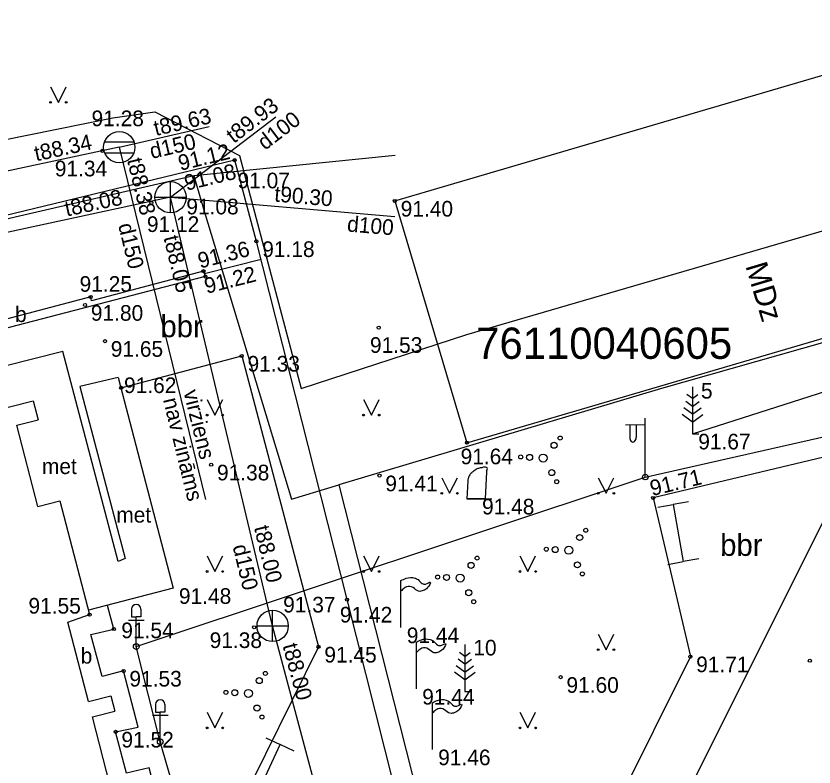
# Model space of a CAD drawing. Extents: x 634272 to 634544, y 247463 to 247653.
# Drawn here: x 634418.64 to 634444.15, y 247588.75 to 247612.76 of the extents above; entities that cross this region are included whole.
import ezdxf

# ---------------------------------------------------------------- set-up
doc = ezdxf.new("R2010")
doc.units = 0
for name, color, linetype in [('APGS_ELEM_####_####_#', 7, 'Continuous'), ('APGS_VADP_ZSPR_####_#', 7, 'Continuous'), ('BUVE_BDET_####_####_#', 7, 'Continuous'), ('BUVE_BDET_####_TKST_#', 7, 'Continuous'), ('BUVE_EKAS_####_####_#', 7, 'Continuous'), ('BUVE_EKAS_RAKS_TKST_#', 7, 'Continuous'), ('BUVE_ELEM_####_####_#', 7, 'Continuous'), ('BUVE_SOLS_####_####_#', 7, 'Continuous'), ('CELI_CAPM_####_####_#', 7, 'Continuous'), ('CELI_CMAL_####_####_#', 7, 'Continuous'), ('CELI_CSEG_####_TKST_#', 7, 'Continuous'), ('LKAN_ELEM_####_####_#', 7, 'Continuous'), ('LKAN_ELEM_PAST_TKST_#', 7, 'Continuous'), ('LKAN_VADP_PAST_####_#', 7, 'Continuous'), ('LKAN_VADP_PAST_TKST_#', 7, 'Continuous'), ('RAMI_UZMR_####_####_#', 7, 'Continuous'), ('RELJ_AATZ_####_TKST_#', 7, 'Continuous'), ('RELJ_ELEM_####_####_#', 7, 'Continuous'), ('ROBZ_KADS_####_TKST_#', 7, 'Continuous'), ('ROBZ_UZMR_####_####_#', 7, 'Continuous'), ('SKAN_ELEM_####_####_#', 7, 'Continuous'), ('SKAN_ELEM_PAST_TKST_#', 7, 'Continuous'), ('SKAN_VADP_PAST_####_#', 7, 'Continuous'), ('SKAN_VADP_PAST_TKST_#', 7, 'Continuous'), ('TERT_DIAM_####_TKST_#', 7, 'Continuous'), ('TERT_ELEM_####_####_#', 7, 'Continuous'), ('TERT_KOKR_####_####_#', 7, 'Continuous')]:
    doc.layers.add(name, color=color, linetype=linetype)

msp = doc.modelspace()

# ---------------------------------------------------------------- linework, layer by layer
at = {"layer": 'APGS_ELEM_####_####_#'}
for p, q in [((634438.755, 247599.687), (634438.12, 247599.682)), ((634438.255, 247599.683), (634438.255, 247599.291)), ((634438.465, 247599.685), (634438.465, 247599.291)), ((634438.755, 247598.02), (634438.755, 247599.903)), ((634422.337, 247593.799), (634422.337, 247593.549)), ((634422.337, 247593.549), (634422.487, 247593.549)), ((634422.487, 247592.599), (634422.487, 247593.549)), ((634422.637, 247593.549), (634422.487, 247593.549)), ((634422.637, 247593.799), (634422.637, 247593.549)), ((634422.237, 247593.449), (634422.737, 247593.449)), ((634423.105, 247590.752), (634423.105, 247590.502)), ((634423.405, 247590.752), (634423.405, 247590.502)), ((634423.105, 247590.502), (634423.255, 247590.502)), ((634423.255, 247589.552), (634423.255, 247590.502)), ((634423.405, 247590.502), (634423.255, 247590.502)), ((634423.005, 247590.402), (634423.505, 247590.402))]:
    msp.add_line(p, q, dxfattribs=at)
for centre, radius in [((634438.755, 247598.02), 0.09), ((634422.487, 247592.599), 0.0907), ((634423.255, 247589.552), 0.0907)]:
    msp.add_circle(centre, radius, dxfattribs=at)
for centre in [(634422.487, 247593.799), (634423.255, 247590.752)]:
    msp.add_arc(centre, 0.15, 0, 180, dxfattribs=at)
msp.add_ellipse((634438.36, 247599.291), major_axis=(0, 0.151), ratio=0.695971, start_param=1.570796, end_param=4.712389, dxfattribs=at)
at = {"layer": 'APGS_VADP_ZSPR_####_#'}
msp.add_lwpolyline([(634424.64, 247564.493), (634427.489, 247567.387), (634428.243, 247568.282), (634428.556, 247569.174), (634428.62, 247569.734), (634428.349, 247570.951), (634427.518, 247573.97), (634425.055, 247583.293), (634424.177, 247586.368), (634423.255, 247589.552), (634422.487, 247592.599), (634438.755, 247598.02), (634453.341, 247601.325), (634455.217, 247592.645), (634458.049, 247580.186), (634460.842, 247567.679), (634446.181, 247564.209)], dxfattribs=at)
at = {"layer": 'BUVE_BDET_####_####_#'}
msp.add_line((634421.062, 247603.658), (634421.031, 247603.777), dxfattribs=at)
for points in [[(634424.638, 247604.603), (634424.692, 247604.432), (634415.797, 247602.116)], [(634424.638, 247604.603), (634421.062, 247603.658)], [(634421.031, 247603.777), (634409.625, 247600.763)], [(634421.911, 247601.206), (634420.687, 247600.92), (634422.13, 247595.421), (634421.912, 247595.323), (634420.138, 247602.03), (634413.732, 247600.418), (634413.69, 247600.52), (634416.369, 247601.213)], [(634421.911, 247601.206), (634423.665, 247594.465), (634420.962, 247593.759)], [(634421.77, 247593.16), (634421.573, 247593.918)], [(634424.519, 247582.466), (634423.79, 247582.308), (634423.459, 247583.653), (634424.19, 247583.849), (634423.711, 247585.639), (634422.99, 247585.469), (634422.619, 247586.777), (634423.356, 247586.952), (634422.897, 247588.72), (634422.18, 247588.555), (634421.828, 247589.872), (634422.546, 247590.02), (634422.083, 247591.821), (634421.394, 247591.641), (634421.036, 247592.981), (634421.77, 247593.16)]]:
    msp.add_lwpolyline(points, dxfattribs=at)
at = {"layer": 'BUVE_EKAS_####_####_#'}
for p, q in [((634418.676, 247599.674), (634419.357, 247599.85)), ((634419.347, 247597.079), (634420.043, 247597.259)), ((634420.958, 247590.842), (634420.303, 247593.378)), ((634420.958, 247590.842), (634421.671, 247591.026)), ((634421.085, 247590.354), (634421.798, 247590.538)), ((634421.763, 247587.727), (634421.085, 247590.354))]:
    msp.add_line(p, q, dxfattribs=at)
for points in [[(634430.752, 247606.848), (634450.886, 247612.763)], [(634430.752, 247606.848), (634433.054, 247599.119)], [(634433.054, 247599.119), (634453.188, 247605.034)], [(634410.243, 247598.168), (634413.566, 247598.866), (634413.511, 247599.021), (634419.188, 247600.462)], [(634419.188, 247600.462), (634419.357, 247599.85)], [(634419.347, 247597.079), (634418.676, 247599.674)], [(634420.043, 247597.259), (634420.998, 247593.62)], [(634420.303, 247593.378), (634420.998, 247593.62)], [(634421.671, 247591.026), (634421.798, 247590.538)]]:
    msp.add_lwpolyline(points, dxfattribs=at)
at = {"layer": 'BUVE_ELEM_####_####_#'}
for p, q in [((634430.947, 247594.372), (634430.947, 247594.709)), ((634430.947, 247593.209), (634430.947, 247594.372)), ((634431.44, 247592.407), (634431.44, 247592.744)), ((634431.44, 247591.244), (634431.44, 247592.407)), ((634431.95, 247590.469), (634431.95, 247590.806)), ((634431.95, 247589.306), (634431.95, 247590.469))]:
    msp.add_line(p, q, dxfattribs=at)
for points in [[(634430.947, 247594.709), (634431.109, 247594.783), (634431.385, 247594.792), (634431.491, 247594.739), (634431.628, 247594.612), (634431.733, 247594.6), (634431.883, 247594.657), (634431.797, 247594.485), (634431.66, 247594.39), (634431.508, 247594.369), (634431.332, 247594.485), (634431.12, 247594.511), (634431.052, 247594.47), (634430.947, 247594.372)], [(634431.44, 247592.744), (634431.602, 247592.818), (634431.878, 247592.827), (634431.984, 247592.774), (634432.121, 247592.647), (634432.226, 247592.635), (634432.376, 247592.692), (634432.29, 247592.52), (634432.153, 247592.425), (634432.001, 247592.404), (634431.825, 247592.52), (634431.613, 247592.546), (634431.545, 247592.505), (634431.44, 247592.407)], [(634431.95, 247590.806), (634432.112, 247590.88), (634432.388, 247590.889), (634432.494, 247590.836), (634432.631, 247590.709), (634432.736, 247590.697), (634432.886, 247590.754), (634432.8, 247590.582), (634432.663, 247590.487), (634432.511, 247590.466), (634432.335, 247590.582), (634432.123, 247590.608), (634432.055, 247590.567), (634431.95, 247590.469)]]:
    msp.add_spline(points, degree=3, dxfattribs=at)
at = {"layer": 'BUVE_SOLS_####_####_#'}
for p, q in [((634439.151, 247597.057), (634439.643, 247597.144)), ((634440.135, 247597.231), (634439.643, 247597.144)), ((634440.46, 247595.402), (634439.968, 247595.315)), ((634439.476, 247595.228), (634439.968, 247595.315)), ((634426.627, 247589.678), (634427.081, 247589.469)), ((634427.535, 247589.26), (634427.081, 247589.469))]:
    msp.add_line(p, q, dxfattribs=at)
for points in [[(634439.643, 247597.144), (634439.968, 247595.315)], [(634426.297, 247587.764), (634427.081, 247589.469)]]:
    msp.add_lwpolyline(points, dxfattribs=at)
at = {"layer": 'CELI_CAPM_####_####_#'}
msp.add_lwpolyline([(634426.327, 247605.556), (634425.634, 247608.152), (634408.658, 247604.045)], dxfattribs=at)
at = {"layer": 'CELI_CMAL_####_####_#'}
msp.add_line((634426.474, 247604.975), (634424.665, 247604.518), dxfattribs=at)
for points in [[(634429.222, 247594.101), (634426.327, 247605.556)], [(634422.006, 247600.872), (634425.858, 247601.892), (634428.312, 247592.59), (634425.762, 247587.434), (634427.131, 247582.006)], [(634454.07, 247600.948), (634439.005, 247597.351), (634440.194, 247592.28), (634435.446, 247582.728), (634431.634, 247584.56), (634429.222, 247594.101)], [(634454.416, 247599.108), (634444.542, 247596.807), (634437.329, 247582.391), (634445.746, 247584.585), (634452.082, 247586.129), (634455.906, 247592.579)]]:
    msp.add_lwpolyline(points, dxfattribs=at)
at = {"layer": 'LKAN_ELEM_####_####_#'}
for p, q in [((634421.478, 247608.741), (634422.414, 247608.741)), ((634421.478, 247608.391), (634422.414, 247608.391))]:
    msp.add_line(p, q, dxfattribs=at)
msp.add_circle((634421.946, 247608.566), 0.5, dxfattribs=at)
at = {"layer": 'LKAN_VADP_PAST_####_#'}
msp.add_line((634421.946, 247608.566), (634424.7, 247597.301), dxfattribs=at)
for points in [[(634421.946, 247608.566), (634424.816, 247609.232)], [(634421.946, 247608.566), (634397.803, 247603.4), (634400.101, 247595.54), (634405.793, 247582.831), (634408.48, 247579.25)]]:
    msp.add_lwpolyline(points, dxfattribs=at)
at = {"layer": 'RAMI_UZMR_####_####_#'}
msp.add_lwpolyline([(634357.63, 247590.775), (634379.264, 247596.642), (634392.424, 247602.216), (634402.994, 247605.715), (634421.735, 247609.504), (634423.082, 247609.702), (634425.783, 247608.304), (634427.755, 247600.855), (634433.048, 247602.581), (634454.806, 247608.92), (634459.819, 247587.798), (634462.766, 247575.147), (634466.614, 247558.36), (634469.076, 247546.545)], dxfattribs=at)
at = {"layer": 'RELJ_ELEM_####_####_#'}
for centre in [(634421.401, 247608.452), (634425.634, 247608.152), (634422.972, 247606.785), (634430.752, 247606.848), (634426.327, 247605.556), (634424.638, 247604.603), (634424.692, 247604.432), (634421.031, 247603.777), (634420.851, 247603.518), (634430.234, 247602.798), (634421.487, 247602.366), (634425.858, 247601.892), (634422.006, 247600.872), (634433.054, 247599.119), (634424.881, 247598.414), (634430.26, 247598.065), (634439.005, 247597.351), (634429.222, 247594.101), (634420.998, 247593.62), (634421.77, 247593.16), (634426.257, 247593.218), (634428.312, 247592.59), (634440.194, 247592.28), (634444.013, 247592.146), (634422.083, 247591.821), (634436.049, 247591.622), (634421.828, 247589.872)]:
    msp.add_circle(centre, 0.05, dxfattribs=at)
at = {"layer": 'ROBZ_UZMR_####_####_#'}
for points in [[(634430.762, 247608.303), (634424.328, 247607.646)], [(634424.328, 247607.646), (634404.114, 247602.967)], [(634424.328, 247607.646), (634424.669, 247606.492)], [(634424.669, 247606.492), (634427.447, 247597.318)], [(634453.433, 247604.869), (634439.274, 247600.849)], [(634439.274, 247600.849), (634428.96, 247597.768)], [(634427.447, 247597.318), (634428.96, 247597.768)], [(634428.96, 247597.768), (634439.705, 247555.341)]]:
    msp.add_lwpolyline(points, dxfattribs=at)
at = {"layer": 'SKAN_ELEM_####_####_#'}
for p, q in [((634423.583, 247606.465), (634423.583, 247607.465)), ((634423.083, 247606.965), (634424.083, 247606.965)), ((634426.846, 247592.759), (634426.846, 247593.759)), ((634426.346, 247593.259), (634427.346, 247593.259))]:
    msp.add_line(p, q, dxfattribs=at)
for centre in [(634423.583, 247606.965), (634426.846, 247593.259)]:
    msp.add_circle(centre, 0.5, dxfattribs=at)
at = {"layer": 'SKAN_VADP_PAST_####_#'}
for q in [(634426.952, 247609.533), (634430.752, 247606.348)]:
    msp.add_line((634423.583, 247606.965), q, dxfattribs=at)
msp.add_lwpolyline([(634467.293, 247556.065), (634460.247, 247556.807), (634435.579, 247559.128), (634432.448, 247572.232), (634426.846, 247593.259), (634423.583, 247606.965), (634413.214, 247604.726), (634403.305, 247602.476), (634405.576, 247593.489), (634409.131, 247581.899)], dxfattribs=at)
at = {"layer": 'TERT_ELEM_####_####_#'}
for p, q in [((634419.75, 247610.5), (634420, 247610)), ((634420, 247610), (634420.25, 247610.5)), ((634440.261, 247600.904), (634440.261, 247599.404)), ((634424.75, 247600.5), (634425, 247600)), ((634425, 247600), (634425.25, 247600.5)), ((634429.75, 247600.5), (634430, 247600)), ((634430, 247600), (634430.25, 247600.5)), ((634440.261, 247600.278), (634440.045, 247600.436)), ((634440.261, 247600.528), (634440.085, 247600.656)), ((634440.261, 247600.528), (634440.435, 247600.656)), ((634440.261, 247600.278), (634440.477, 247600.436)), ((634440.261, 247600.028), (634439.983, 247600.232)), ((634440.261, 247600.028), (634440.539, 247600.232)), ((634440.261, 247599.778), (634439.929, 247600.022)), ((634440.261, 247599.778), (634440.595, 247600.022)), ((634440.261, 247599.404), (634440.461, 247599.404)), ((634433.652, 247597.325), (634433.686, 247598.19)), ((634432.25, 247598), (634432.5, 247597.5)), ((634432.5, 247597.5), (634432.75, 247598)), ((634433.083, 247597.898), (634433.052, 247597.325)), ((634437.25, 247598), (634437.5, 247597.5)), ((634437.5, 247597.5), (634437.75, 247598)), ((634433.652, 247597.325), (634433.052, 247597.325)), ((634433.052, 247597.325), (634433.352, 247597.325)), ((634433.352, 247597.325), (634433.652, 247597.325)), ((634433.652, 247597.325), (634433.852, 247597.325)), ((634424.75, 247595.5), (634425, 247595)), ((634425, 247595), (634425.25, 247595.5)), ((634429.75, 247595.5), (634430, 247595)), ((634430, 247595), (634430.25, 247595.5)), ((634434.75, 247595.5), (634435, 247595)), ((634435, 247595), (634435.25, 247595.5)), ((634437.25, 247593), (634437.5, 247592.5)), ((634437.5, 247592.5), (634437.75, 247593)), ((634432.988, 247592.661), (634432.988, 247591.161)), ((634432.988, 247592.285), (634432.812, 247592.413)), ((634432.988, 247592.285), (634433.162, 247592.413)), ((634432.988, 247592.035), (634432.772, 247592.193)), ((634432.988, 247592.035), (634433.204, 247592.193)), ((634432.988, 247591.535), (634432.656, 247591.779)), ((634432.988, 247591.785), (634432.71, 247591.989)), ((634432.988, 247591.785), (634433.266, 247591.989)), ((634432.988, 247591.535), (634433.322, 247591.779)), ((634432.988, 247591.161), (634433.188, 247591.161)), ((634424.75, 247590.5), (634425, 247590)), ((634425, 247590), (634425.25, 247590.5)), ((634434.75, 247590.5), (634435, 247590)), ((634435, 247590), (634435.25, 247590.5))]:
    msp.add_line(p, q, dxfattribs=at)
for centre, radius in [((634419.75, 247610), 0.028), ((634420.25, 247610), 0.0263), ((634424.75, 247600), 0.028), ((634425.25, 247600), 0.0263), ((634429.75, 247600), 0.028), ((634430.25, 247600), 0.0263), ((634436.034, 247599.267), 0.064), ((634435.838, 247599.036), 0.096), ((634434.772, 247598.662), 0.064), ((634435.056, 247598.649), 0.096), ((634435.49, 247598.628), 0.128), ((634435.766, 247598.161), 0.096), ((634435.924, 247597.872), 0.064), ((634432.25, 247597.5), 0.028), ((634432.75, 247597.5), 0.0263), ((634437.25, 247597.5), 0.028), ((634437.75, 247597.5), 0.0263), ((634436.853, 247596.318), 0.064), ((634436.657, 247596.087), 0.096), ((634435.591, 247595.713), 0.064), ((634435.875, 247595.7), 0.096), ((634436.309, 247595.679), 0.128), ((634433.381, 247595.428), 0.064), ((634433.185, 247595.197), 0.096), ((634436.585, 247595.212), 0.096), ((634424.75, 247595), 0.028), ((634425.25, 247595), 0.0263), ((634429.75, 247595), 0.028), ((634430.25, 247595), 0.0263), ((634432.119, 247594.823), 0.064), ((634432.403, 247594.81), 0.096), ((634432.837, 247594.789), 0.128), ((634434.75, 247595), 0.028), ((634435.25, 247595), 0.0263), ((634436.743, 247594.923), 0.064), ((634433.113, 247594.322), 0.096), ((634433.271, 247594.033), 0.064), ((634437.25, 247592.5), 0.028), ((634437.75, 247592.5), 0.0263), ((634426.614, 247591.741), 0.064), ((634426.418, 247591.51), 0.096), ((634425.352, 247591.136), 0.064), ((634425.636, 247591.123), 0.096), ((634426.07, 247591.102), 0.128), ((634426.346, 247590.635), 0.096), ((634426.504, 247590.346), 0.064), ((634424.75, 247590), 0.028), ((634425.25, 247590), 0.0263), ((634434.75, 247590), 0.028), ((634435.25, 247590), 0.0263)]:
    msp.add_circle(centre, radius, dxfattribs=at)
msp.add_spline([(634433.686, 247598.19), (634433.69, 247598.221), (634433.693, 247598.232), (634433.708, 247598.294), (634433.678, 247598.329), (634433.556, 247598.323), (634433.452, 247598.305), (634433.346, 247598.266), (634433.281, 247598.222), (634433.206, 247598.158), (634433.126, 247598.06), (634433.095, 247597.971), (634433.083, 247597.897)], degree=3, dxfattribs=at)
at = {"layer": 'TERT_KOKR_####_####_#'}
msp.add_lwpolyline([(634440.261, 247599.404), (634452.282, 247603.254)], dxfattribs=at)

# ---------------------------------------------------------------- texts
at = {"layer": 'BUVE_BDET_####_TKST_#'}
for s, p in [('b', (634418.615, 247602.976)), ('met', (634419.473, 247598.116)), ('met', (634421.849, 247596.563)), ('b', (634420.711, 247592.056))]:
    msp.add_text(s, height=0.5, dxfattribs=at).set_placement(p)
at = {"layer": 'BUVE_EKAS_RAKS_TKST_#'}
msp.add_text('MDz', height=0.7, rotation=286.5856, dxfattribs=at).set_placement((634441.949, 247604.775))
at = {"layer": 'CELI_CSEG_####_TKST_#'}
for p in [(634423.261, 247602.491), (634441.148, 247595.499)]:
    msp.add_text('bbr', height=0.7, dxfattribs=at).set_placement(p)
at = {"layer": 'LKAN_ELEM_PAST_TKST_#'}
msp.add_text(' 91.28', height=0.5, dxfattribs=at).set_placement((634420.873, 247609.239))
at = {"layer": 'LKAN_VADP_PAST_TKST_#'}
for s, rotation, p in [('t89.63', 13.0594, (634423.111, 247608.923)), ('t88.34', 12.0777, (634419.288, 247608.113)), ('d150', 13.0594, (634422.981, 247608.19)), ('t88.38', 283.7385, (634422.19, 247608.158)), ('d150', 283.7385, (634421.906, 247606.078)), ('virziens', 283.7385, (634423.992, 247600.749)), ('nav zināms', 283.7385, (634423.34, 247600.496))]:
    msp.add_text(s, height=0.5, rotation=rotation, dxfattribs=at).set_placement(p)
at = {"layer": 'RELJ_AATZ_####_TKST_#'}
for s, rotation, p in [(' 91.12', 13.6002, (634423.715, 247607.766)), (' 91.08', 13.6002, (634423.912, 247607.129)), (' 91.36', 14.1833, (634424.347, 247604.64)), (' 91.22', 14.1833, (634424.555, 247603.832)), (' 91.71', 13.4288, (634438.789, 247597.367))]:
    msp.add_text(s, height=0.5, rotation=rotation, dxfattribs=at).set_placement(p)
for s, p in [(' 91.34', (634419.699, 247607.635)), (' 91.07', (634425.538, 247607.252)), (' 91.40', (634430.752, 247606.348)), (' 91.12', (634422.642, 247605.856)), (' 91.18', (634426.327, 247605.056)), (' 91.25', (634420.491, 247603.943)), (' 91.80', (634420.851, 247603.018)), (' 91.53', (634429.77, 247601.991)), (' 91.65', (634421.487, 247601.866)), (' 91.33', (634425.858, 247601.392)), (' 91.62', (634421.911, 247600.706)), (' 91.67', (634440.261, 247598.904)), (' 91.64', (634432.667, 247598.429)), (' 91.38', (634424.881, 247597.914)), (' 91.41', (634430.26, 247597.565)), (' 91.48', (634433.352, 247596.825)), (' 91.48', (634423.665, 247593.965)), (' 91.55', (634418.857, 247593.654)), (' 91.42', (634428.809, 247593.369)), (' 91.54', (634421.824, 247592.867)), (' 91.38', (634424.647, 247592.554)), (' 91.44', (634430.947, 247592.709)), (' 91.45', (634428.312, 247592.09)), (' 91.71', (634440.194, 247591.78)), (' 91.53', (634422.083, 247591.321)), (' 91.60', (634436.049, 247591.122)), (' 91.44', (634431.44, 247590.744)), (' 91.52', (634421.828, 247589.372)), (' 91.46', (634431.95, 247588.806))]:
    msp.add_text(s, height=0.5, dxfattribs=at).set_placement(p)
at = {"layer": 'ROBZ_KADS_####_TKST_#'}
msp.add_text('76110040605', height=1, dxfattribs=at).set_placement((634433.35, 247601.799))
at = {"layer": 'SKAN_ELEM_PAST_TKST_#'}
for s, p in [(' 91.08', (634423.901, 247606.419)), (' 91.37', (634426.996, 247593.69))]:
    msp.add_text(s, height=0.5, dxfattribs=at).set_placement(p)
at = {"layer": 'SKAN_VADP_PAST_TKST_#'}
for s, rotation, p in [('t89.93', 37.3157, (634425.603, 247608.67)), ('d100', 37.3157, (634426.601, 247608.452)), ('t88.08', 12.1849, (634420.263, 247606.347)), ('t90.30', 355.081, (634426.887, 247606.831)), ('d100', 355.081, (634429.211, 247605.874)), ('t88.05', 283.3912, (634423.357, 247605.682)), ('t88.00', 283.3912, (634426.246, 247596.41)), ('d150', 283.3912, (634425.565, 247595.807)), ('t88.00', 284.9182, (634427.16, 247592.634))]:
    msp.add_text(s, height=0.5, rotation=rotation, dxfattribs=at).set_placement(p)
at = {"layer": 'TERT_DIAM_####_TKST_#'}
for s, p in [('5', (634440.533, 247600.529)), ('10', (634433.259, 247592.315))]:
    msp.add_text(s, height=0.5, dxfattribs=at).set_placement(p)

doc.saveas('drawing.dxf')
